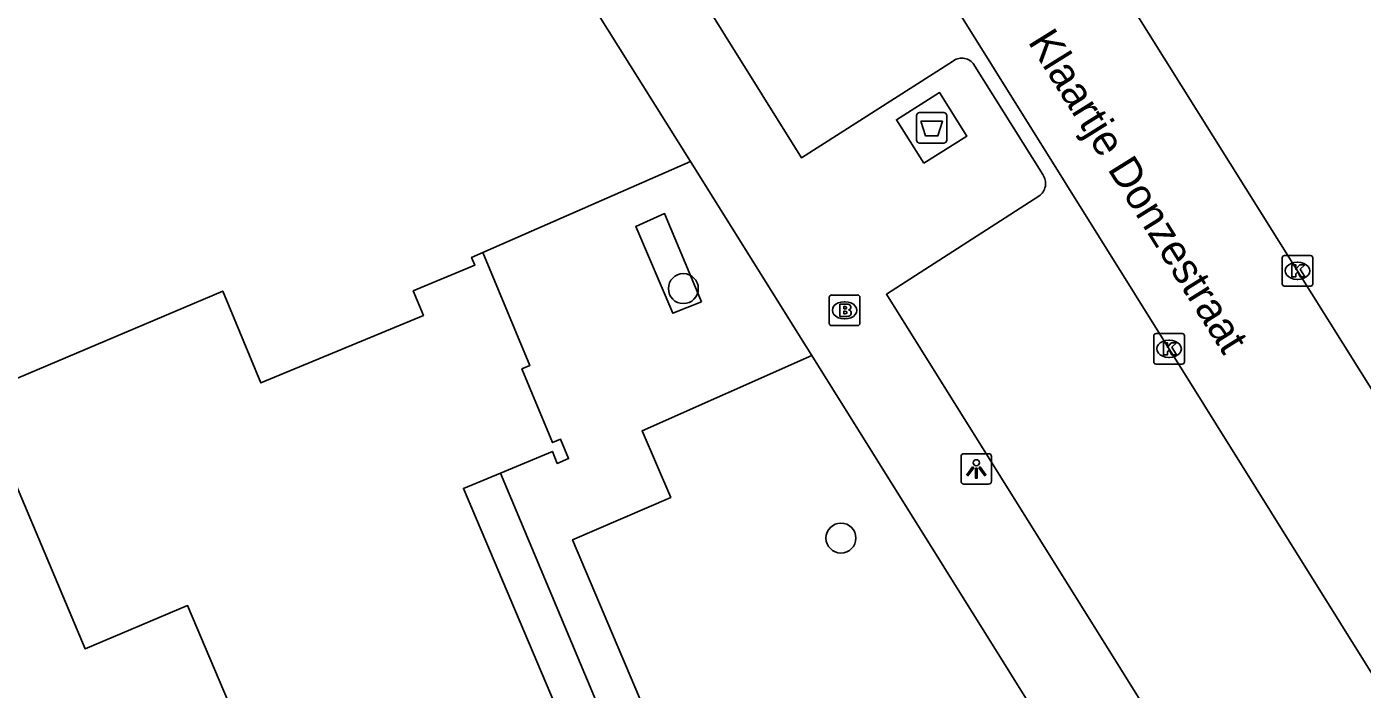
# Model space of a CAD drawing. Extents: x 160077 to 160945, y 386481 to 387498.
# Drawn here: x 160283.4 to 160327.02, y 387056.77 to 387078.43 of the extents above; entities that cross this region are included whole.
import ezdxf

# ---------------------------------------------------------------- set-up
doc = ezdxf.new("R2010")
doc.units = 0
for name, color, linetype in [('IMGEO_Afval_apart_plaats', 7, 'Continuous'), ('IMGEO_Boom', 7, 'Continuous'), ('IMGEO_Brandkraan', 7, 'Continuous'), ('IMGEO_Kolk', 7, 'Continuous'), ('IMGEO_Lichtpunt', 7, 'Continuous'), ('IMGEO_Openbare_ruimte_label', 7, 'Continuous'), ('IMGEO_Pand', 7, 'Continuous'), ('IMGEO_Rijbaan_lokaal_open', 7, 'Continuous'), ('IMGEO_Voetpad_gesloten', 7, 'Continuous'), ('IMGEO_Voetpad_open', 7, 'Continuous')]:
    doc.layers.add(name, color=color, linetype=linetype)

msp = doc.modelspace()

# ---------------------------------------------------------------- linework, layer by layer
at = {"layer": 'IMGEO_Afval_apart_plaats'}
for p, q in [((160312.46, 387074.718), (160312.46, 387075.518)), ((160312.46, 387075.518), (160312.46, 387074.718)), ((160312.56, 387075.618), (160313.35, 387075.618)), ((160313.35, 387075.618), (160312.56, 387075.618)), ((160313.45, 387075.518), (160313.45, 387074.718)), ((160313.45, 387074.718), (160313.45, 387075.518)), ((160313.35, 387074.618), (160312.56, 387074.618)), ((160312.56, 387074.618), (160313.35, 387074.618))]:
    msp.add_line(p, q, dxfattribs=at)
msp.add_lwpolyline([(160312.603, 387075.332), (160313.307, 387075.332), (160313.158, 387074.862), (160312.752, 387074.862), (160312.603, 387075.332)], dxfattribs=at)
for centre, start, end in [((160312.56, 387075.518), 90, 180), ((160312.56, 387075.518), 90, 180), ((160313.35, 387075.518), 0, 90), ((160313.35, 387075.518), 360, 90), ((160312.56, 387074.718), 180, 270), ((160312.56, 387074.718), 180, 270), ((160313.35, 387074.718), 270, 0), ((160313.35, 387074.718), 270, 0)]:
    msp.add_arc(centre, 0.1, start, end, dxfattribs=at)
at = {"layer": 'IMGEO_Boom'}
for centre in [(160304.846, 387069.864), (160309.994, 387061.71)]:
    msp.add_circle(centre, 0.489, dxfattribs=at)
at = {"layer": 'IMGEO_Brandkraan'}
for p, q in [((160309.612, 387068.729), (160309.612, 387069.581)), ((160309.687, 387069.655), (160310.539, 387069.655)), ((160310.1, 387069.435), (160310.125, 387069.435)), ((160310.613, 387069.581), (160310.613, 387068.729)), ((160310.539, 387068.655), (160309.687, 387068.655)), ((160310.123, 387068.875), (160310.098, 387068.875))]:
    msp.add_line(p, q, dxfattribs=at)
for points in [[(160309.612, 387068.729), (160309.612, 387069.581)], [(160309.687, 387069.655), (160310.539, 387069.655)], [(160310.613, 387069.581), (160310.613, 387068.729)], [(160309.96, 387069.355), (160309.96, 387068.955), (160310.173, 387068.955)], [(160310.191, 387069.355), (160309.96, 387069.355)], [(160310.139, 387069.274), (160310.085, 387069.274), (160310.085, 387069.198)], [(160310.085, 387069.198), (160310.138, 387069.198)], [(160310.147, 387069.122), (160310.085, 387069.122), (160310.085, 387069.041)], [(160310.085, 387069.041), (160310.147, 387069.041)], [(160310.539, 387068.655), (160309.687, 387068.655)]]:
    msp.add_lwpolyline(points, dxfattribs=at)
for centre, radius, start, end in [((160309.689, 387069.579), 0.0765, 91.552, 178.448), ((160309.689, 387069.579), 0.0765, 91.552, 178.448), ((160310.537, 387069.579), 0.0765, 1.552, 88.448), ((160310.537, 387069.579), 0.0765, 1.552, 88.448), ((160310.14, 387069.236), 0.0379, 267.8285, 90.9355), ((160310.148, 387069.081), 0.0404, 269.8759, 90.5077), ((160310.179, 387069.206), 0.251, 268.6676, 293.5347), ((160310.195, 387069.21), 0.145, 59.4692, 91.5367), ((160310.22, 387069.257), 0.0922, 285.5137, 58.1501), ((160310.225, 387069.065), 0.105, 301.3115, 78.989), ((160309.689, 387068.731), 0.0765, 181.552, 268.448), ((160309.689, 387068.731), 0.0765, 181.552, 268.448), ((160310.537, 387068.731), 0.0765, 271.552, 358.448), ((160310.537, 387068.731), 0.0765, 271.552, 358.448)]:
    msp.add_arc(centre, radius, start, end, dxfattribs=at)
for centre, major_axis, ratio, start_param, end_param in [((160310.099, 387069.155), (-0.387, 0.002), 0.722429, 4.712389, 7.853982), ((160310.124, 387069.155), (-0.39, 0.002), 0.717154, 1.570796, 4.712389)]:
    msp.add_ellipse(centre, major_axis=major_axis, ratio=ratio, start_param=start_param, end_param=end_param, dxfattribs=at)
at = {"layer": 'IMGEO_Kolk'}
for p, q in [((160324.403, 387070.02), (160324.403, 387070.872)), ((160324.478, 387070.946), (160325.33, 387070.946)), ((160324.891, 387070.726), (160324.916, 387070.726)), ((160325.404, 387070.872), (160325.404, 387070.02)), ((160325.33, 387069.946), (160324.478, 387069.946)), ((160324.914, 387070.166), (160324.889, 387070.166)), ((160320.209, 387067.47), (160320.209, 387068.322)), ((160320.284, 387068.396), (160321.136, 387068.396)), ((160320.697, 387068.176), (160320.722, 387068.176)), ((160321.21, 387068.322), (160321.21, 387067.47)), ((160321.136, 387067.396), (160320.284, 387067.396)), ((160320.72, 387067.616), (160320.695, 387067.616))]:
    msp.add_line(p, q, dxfattribs=at)
for points in [[(160324.403, 387070.02), (160324.403, 387070.872)], [(160324.478, 387070.946), (160325.33, 387070.946)], [(160325.404, 387070.872), (160325.404, 387070.02)], [(160324.724, 387070.646), (160324.847, 387070.646), (160324.847, 387070.495), (160324.977, 387070.646), (160325.141, 387070.646), (160324.995, 387070.495), (160325.148, 387070.246), (160324.996, 387070.246), (160324.911, 387070.41), (160324.847, 387070.343), (160324.847, 387070.246), (160324.724, 387070.246), (160324.724, 387070.646)], [(160325.33, 387069.946), (160324.478, 387069.946)], [(160320.209, 387067.47), (160320.209, 387068.322)], [(160320.284, 387068.396), (160321.136, 387068.396)], [(160320.53, 387068.096), (160320.653, 387068.096), (160320.653, 387067.945), (160320.783, 387068.096), (160320.947, 387068.096), (160320.801, 387067.945), (160320.954, 387067.696), (160320.802, 387067.696), (160320.717, 387067.86), (160320.653, 387067.793), (160320.653, 387067.696), (160320.53, 387067.696), (160320.53, 387068.096)], [(160321.21, 387068.322), (160321.21, 387067.47)], [(160321.136, 387067.396), (160320.284, 387067.396)]]:
    msp.add_lwpolyline(points, dxfattribs=at)
for centre, start, end in [((160324.48, 387070.87), 91.552, 178.448), ((160324.48, 387070.87), 91.552, 178.448), ((160325.328, 387070.87), 1.552, 88.448), ((160325.328, 387070.87), 1.552, 88.448), ((160324.48, 387070.022), 181.552, 268.448), ((160324.48, 387070.022), 181.552, 268.448), ((160325.328, 387070.022), 271.552, 358.448), ((160325.328, 387070.022), 271.552, 358.448), ((160320.286, 387068.32), 91.552, 178.448), ((160320.286, 387068.32), 91.552, 178.448), ((160321.134, 387068.32), 1.552, 88.448), ((160321.134, 387068.32), 1.552, 88.448), ((160320.286, 387067.472), 181.552, 268.448), ((160320.286, 387067.472), 181.552, 268.448), ((160321.134, 387067.472), 271.552, 358.448), ((160321.134, 387067.472), 271.552, 358.448)]:
    msp.add_arc(centre, 0.0765, start, end, dxfattribs=at)
for centre, major_axis, ratio, start_param, end_param in [((160324.89, 387070.446), (-0.387, 0.002), 0.722429, 4.712389, 7.853982), ((160324.915, 387070.446), (-0.39, 0.002), 0.717154, 1.570796, 4.712389), ((160320.696, 387067.896), (-0.387, 0.002), 0.722429, 4.712389, 7.853982), ((160320.721, 387067.896), (-0.39, 0.002), 0.717154, 1.570796, 4.712389)]:
    msp.add_ellipse(centre, major_axis=major_axis, ratio=ratio, start_param=start_param, end_param=end_param, dxfattribs=at)
at = {"layer": 'IMGEO_Lichtpunt'}
for p, q in [((160313.915, 387064.374), (160313.915, 387063.567)), ((160313.915, 387064.374), (160313.915, 387063.567)), ((160314.817, 387064.469), (160314.009, 387064.469)), ((160314.817, 387064.469), (160314.009, 387064.469)), ((160314.911, 387063.567), (160314.911, 387064.374)), ((160314.911, 387063.567), (160314.911, 387064.374)), ((160314.009, 387063.473), (160314.817, 387063.473)), ((160314.009, 387063.473), (160314.817, 387063.473))]:
    msp.add_line(p, q, dxfattribs=at)
for points in [[(160314.289, 387064.038), (160314.328, 387064.01), (160314.14, 387063.748), (160314.102, 387063.775), (160314.289, 387064.038)], [(160314.391, 387063.99), (160314.438, 387063.99), (160314.438, 387063.668), (160314.391, 387063.668), (160314.391, 387063.99)], [(160314.501, 387064.01), (160314.539, 387064.037), (160314.726, 387063.775), (160314.687, 387063.747), (160314.501, 387064.01)]]:
    msp.add_lwpolyline(points, dxfattribs=at)
msp.add_circle((160314.414, 387064.172), 0.0994, dxfattribs=at)
for centre, start, end in [((160314.009, 387064.374), 90, 180), ((160314.009, 387064.374), 90, 180), ((160314.817, 387064.374), 0, 90), ((160314.817, 387064.374), 0, 90), ((160314.009, 387063.567), 180, 270), ((160314.009, 387063.567), 180, 270), ((160314.817, 387063.567), 270, 0), ((160314.817, 387063.567), 270, 360)]:
    msp.add_arc(centre, 0.0946, start, end, dxfattribs=at)
at = {"layer": 'IMGEO_Pand'}
for points in [[(160298.298, 387071.04), (160297.928, 387070.885), (160298.035, 387070.627), (160296.023, 387069.791), (160296.357, 387068.987), (160291.051, 387066.783), (160289.805, 387069.781), (160281.799, 387066.389), (160285.315, 387058.089), (160288.652, 387059.502), (160310.605, 387007.683), (160315.35, 387009.693)], [(160298.877, 387063.837), (160300.57, 387064.54), (160300.73, 387064.152), (160301.098, 387064.306), (160300.834, 387064.942), (160300.575, 387064.834), (160299.574, 387067.241), (160299.832, 387067.349), (160298.298, 387071.04)], [(160320.521, 387012.204), (160319.506, 387011.774), (160297.664, 387063.334), (160298.877, 387063.837)]]:
    msp.add_lwpolyline(points, dxfattribs=at)
at = {"layer": 'IMGEO_Rijbaan_lokaal_open'}
for points in [[(160308.312, 387087.772), (160328.585, 387055.274), (160352.547, 387016.942)], [(160314.192, 387087.558), (160327.471, 387066.343), (160347.453, 387034.413)]]:
    msp.add_lwpolyline(points, dxfattribs=at)
at = {"layer": 'IMGEO_Voetpad_gesloten'}
msp.add_lwpolyline([(160312.695, 387073.966), (160311.804, 387075.384), (160313.214, 387076.27), (160314.105, 387074.852), (160312.695, 387073.966)], dxfattribs=at)
at = {"layer": 'IMGEO_Voetpad_open'}
for points in [[(160313.636, 387077.284), (160308.704, 387074.139), (160299.657, 387088.656), (160306.562, 387092.944), (160306.662, 387093.07), (160306.75, 387093.204), (160306.825, 387093.346), (160306.888, 387093.493), (160306.938, 387093.646), (160306.963, 387093.751)], [(160295.34, 387089.573), (160305.079, 387074.014)], [(160316.586, 387073.589), (160314.309, 387077.22)], [(160298.298, 387071.04), (160305.079, 387074.014)], [(160305.079, 387074.014), (160308.857, 387067.977), (160309.043, 387067.68)], [(160342.585, 387019.867), (160311.479, 387069.679), (160316.457, 387072.888)], [(160305.441, 387069.432), (160304.232, 387072.315), (160303.291, 387071.896), (160304.505, 387069.056), (160305.441, 387069.432)], [(160326.961, 387000.883), (160324.051, 387007.52), (160325.476, 387008.122), (160324.258, 387011.006), (160322.921, 387010.441), (160301.226, 387061.655), (160304.436, 387063.04), (160303.501, 387065.215), (160309.043, 387067.68)], [(160309.043, 387067.68), (160339.387, 387019.061), (160344.043, 387011.607), (160326.961, 387000.883)], [(160320.521, 387012.204), (160298.877, 387063.837)]]:
    msp.add_lwpolyline(points, dxfattribs=at)
for centre, radius, start, end in [((160313.942, 387076.931), 0.467, 38.2374, 130.898), ((160316.179, 387073.302), 0.498, 303.9099, 35.236)]:
    msp.add_arc(centre, radius, start, end, dxfattribs=at)

# ---------------------------------------------------------------- texts
at = {"layer": 'IMGEO_Openbare_ruimte_label'}
msp.add_text('Klaartje Donzestraat', height=1, rotation=302.0054, dxfattribs=at).set_placement((160316.081, 387077.935))

doc.saveas('drawing.dxf')
